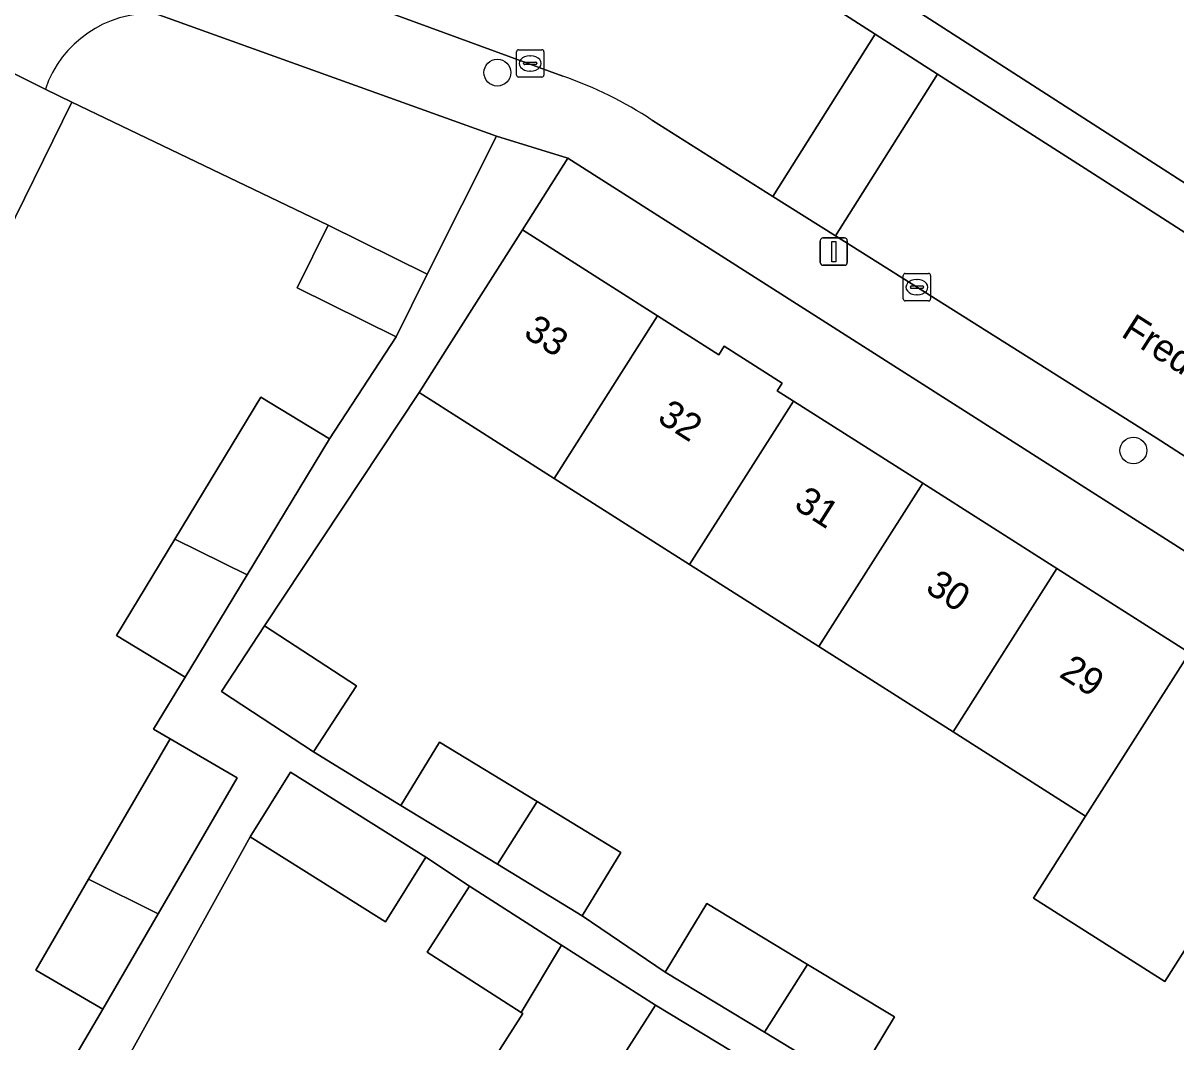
# Model space of a CAD drawing. Extents: x 160102 to 160934, y 382045 to 382923.
# Drawn here: x 160360.74 to 160402.88, y 382289.36 to 382326.59 of the extents above; entities that cross this region are included whole.
import ezdxf

# ---------------------------------------------------------------- set-up
doc = ezdxf.new("R2010")
doc.units = 0
for name, color, linetype in [('IMGEO_Boom', 7, 'Continuous'), ('IMGEO_Erf', 7, 'Continuous'), ('IMGEO_Groenvoorziening', 7, 'Continuous'), ('IMGEO_Kolk', 7, 'Continuous'), ('IMGEO_Lichtmast', 7, 'Continuous'), ('IMGEO_Openbare_ruimte_label', 7, 'Continuous'), ('IMGEO_Pand', 7, 'Continuous'), ('IMGEO_Pand_nummerreeks', 7, 'Continuous'), ('IMGEO_Rijbaan_lokaal_open', 7, 'Continuous'), ('IMGEO_Voetpad_open', 7, 'Continuous')]:
    doc.layers.add(name, color=color, linetype=linetype)

msp = doc.modelspace()

# ---------------------------------------------------------------- linework, layer by layer
at = {"layer": 'IMGEO_Boom'}
for centre in [(160378.074, 382324.78), (160401.321, 382310.971)]:
    msp.add_circle(centre, 0.489, dxfattribs=at)
at = {"layer": 'IMGEO_Erf'}
for points in [[(160366.666, 382302.692), (160364.152, 382304.216), (160366.28, 382307.729), (160369.425, 382312.919), (160371.939, 382311.396), (160374.379, 382315.121), (160370.755, 382316.911), (160371.89, 382319.21), (160362.523, 382323.7), (160359.744, 382318.076), (160359.198, 382317.036), (160358.065, 382314.742), (160360.27, 382313.652), (160359.092, 382311.269), (160359.529, 382311.053), (160356.868, 382305.666), (160354.057, 382299.975), (160351.44, 382301.267), (160348.559, 382295.436), (160345.757, 382289.765), (160342.922, 382291.166)], [(160404.372, 382294.56), (160402.466, 382291.561), (160397.668, 382294.61), (160399.574, 382297.609), (160394.734, 382300.685), (160389.827, 382303.803), (160385.101, 382306.807), (160380.151, 382309.953), (160375.213, 382313.091), (160369.561, 382304.569), (160372.929, 382302.375), (160371.358, 382299.964), (160374.551, 382297.996), (160375.956, 382300.308), (160379.525, 382298.139), (160382.583, 382296.281), (160381.178, 382293.969), (160384.206, 382291.908), (160385.728, 382294.422), (160389.415, 382292.19), (160392.59, 382290.269), (160391.068, 382287.755)], [(160344.039, 382286.352), (160356.664, 382278.779), (160358.695, 382282.138), (160355.236, 382284.213), (160356.54, 382286.388), (160359.999, 382284.313), (160360.175, 382284.614), (160355.353, 382287.424), (160357.305, 382290.773), (160362.134, 382287.959), (160363.655, 382290.557), (160361.206, 382291.98), (160363.135, 382295.3), (160366.118, 382300.431), (160365.51, 382300.785), (160366.666, 382302.692)], [(160377.525, 382288.071), (160379.001, 382290.4), (160378.944, 382290.437), (160375.51, 382292.635), (160377.056, 382295.05), (160375.46, 382296.106), (160373.982, 382293.75), (160371.619, 382295.234), (160369.034, 382296.857), (160363.795, 382287.392)], [(160386.658, 382289.004), (160383.854, 382290.698), (160380.822, 382285.961)]]:
    msp.add_lwpolyline(points, dxfattribs=at)
msp.add_lwpolyline([(160380.656, 382321.65), (160378.99, 382319.034), (160383.927, 382315.896), (160386.169, 382314.471), (160386.366, 382314.781), (160388.486, 382313.433), (160388.307, 382313.152), (160388.895, 382312.778), (160393.622, 382309.774), (160398.528, 382306.656), (160403.368, 382303.58), (160408.166, 382300.531), (160413.128, 382297.377), (160418.16, 382294.179), (160419.783, 382296.727)], close=True, dxfattribs=at)
at = {"layer": 'IMGEO_Groenvoorziening'}
msp.add_lwpolyline([(160437.773, 382324.41), (160408.75, 382345.566), (160387.099, 382331.11), (160425.707, 382306.276)], close=True, dxfattribs=at)
msp.add_lwpolyline([(160361.552, 382324.18), (160362.523, 382323.7), (160371.89, 382319.21), (160375.514, 382317.42), (160378.037, 382322.453), (160365.563, 382326.947)], dxfattribs=at)
msp.add_arc((160365.426, 382322.855), 4.094, 88.0823, 161.1176, dxfattribs=at)
at = {"layer": 'IMGEO_Kolk'}
for p, q in [((160378.85, 382325.617), (160379.702, 382325.617)), ((160378.775, 382324.691), (160378.775, 382325.543)), ((160379.077, 382325.16), (160379.475, 382325.16)), ((160379.263, 382325.397), (160379.288, 382325.397)), ((160379.776, 382325.543), (160379.776, 382324.691)), ((160379.034, 382325.111), (160379.034, 382325.123)), ((160379.472, 382325.074), (160379.074, 382325.074)), ((160379.286, 382324.837), (160379.261, 382324.837)), ((160379.518, 382325.123), (160379.518, 382325.111)), ((160379.702, 382324.617), (160378.85, 382324.617)), ((160392.91, 382316.514), (160392.91, 382317.366)), ((160392.985, 382317.44), (160393.837, 382317.44)), ((160393.398, 382317.22), (160393.423, 382317.22)), ((160393.911, 382317.366), (160393.911, 382316.514)), ((160393.169, 382316.934), (160393.169, 382316.946)), ((160393.607, 382316.897), (160393.209, 382316.897)), ((160393.212, 382316.983), (160393.61, 382316.983)), ((160393.653, 382316.946), (160393.653, 382316.934)), ((160393.837, 382316.44), (160392.985, 382316.44)), ((160393.421, 382316.66), (160393.396, 382316.66))]:
    msp.add_line(p, q, dxfattribs=at)
for points in [[(160378.85, 382325.617), (160379.702, 382325.617)], [(160378.775, 382324.691), (160378.775, 382325.543)], [(160379.776, 382325.543), (160379.776, 382324.691)], [(160379.702, 382324.617), (160378.85, 382324.617)], [(160392.91, 382316.514), (160392.91, 382317.366)], [(160392.985, 382317.44), (160393.837, 382317.44)], [(160393.911, 382317.366), (160393.911, 382316.514)], [(160393.837, 382316.44), (160392.985, 382316.44)]]:
    msp.add_lwpolyline(points, dxfattribs=at)
for centre, radius, start, end in [((160378.852, 382325.541), 0.0765, 91.552, 178.448), ((160378.852, 382325.541), 0.0765, 91.552, 178.448), ((160379.7, 382325.541), 0.0765, 1.552, 88.448), ((160379.7, 382325.541), 0.0765, 1.552, 88.448), ((160379.074, 382325.12), 0.0403, 85.8775, 175.7526), ((160379.479, 382325.122), 0.0386, 1.7309, 96.639), ((160379.071, 382325.11), 0.0366, 178.938, 274.7102), ((160379.475, 382325.117), 0.043, 264.8664, 352.4533), ((160378.852, 382324.693), 0.0765, 181.552, 268.448), ((160378.852, 382324.693), 0.0765, 181.552, 268.448), ((160379.7, 382324.693), 0.0765, 271.552, 358.448), ((160379.7, 382324.693), 0.0765, 271.552, 358.448), ((160392.987, 382317.364), 0.0765, 91.552, 178.448), ((160392.987, 382317.364), 0.0765, 91.552, 178.448), ((160393.835, 382317.364), 0.0765, 1.552, 88.448), ((160393.835, 382317.364), 0.0765, 1.552, 88.448), ((160393.209, 382316.943), 0.0403, 85.8775, 175.7526), ((160393.206, 382316.933), 0.0366, 178.938, 274.7102), ((160393.61, 382316.94), 0.043, 264.8664, 352.4533), ((160393.614, 382316.945), 0.0386, 1.7309, 96.639), ((160392.987, 382316.516), 0.0765, 181.552, 268.448), ((160392.987, 382316.516), 0.0765, 181.552, 268.448), ((160393.835, 382316.516), 0.0765, 271.552, 358.448), ((160393.835, 382316.516), 0.0765, 271.552, 358.448)]:
    msp.add_arc(centre, radius, start, end, dxfattribs=at)
for centre, major_axis, ratio, start_param, end_param in [((160379.262, 382325.117), (-0.387, 0.002), 0.722429, 4.712389, 7.853982), ((160379.287, 382325.117), (-0.39, 0.002), 0.717154, 1.570796, 4.712389), ((160393.397, 382316.94), (-0.387, 0.002), 0.722429, 4.712389, 7.853982), ((160393.422, 382316.94), (-0.39, 0.002), 0.717154, 1.570796, 4.712389)]:
    msp.add_ellipse(centre, major_axis=major_axis, ratio=ratio, start_param=start_param, end_param=end_param, dxfattribs=at)
at = {"layer": 'IMGEO_Lichtmast'}
for p, q in [((160389.876, 382317.839), (160389.876, 382318.639)), ((160389.876, 382318.639), (160389.876, 382317.839)), ((160389.976, 382318.739), (160390.766, 382318.739)), ((160390.766, 382318.739), (160389.976, 382318.739)), ((160390.866, 382318.639), (160390.866, 382317.839)), ((160390.866, 382317.839), (160390.866, 382318.639)), ((160390.766, 382317.739), (160389.976, 382317.739)), ((160389.976, 382317.739), (160390.766, 382317.739))]:
    msp.add_line(p, q, dxfattribs=at)
msp.add_lwpolyline([(160390.296, 382318.614), (160390.446, 382318.614), (160390.446, 382317.864), (160390.296, 382317.864), (160390.296, 382318.614)], dxfattribs=at)
for centre, start, end in [((160389.976, 382318.639), 90, 180), ((160389.976, 382318.639), 90, 180), ((160390.766, 382318.639), 0, 90), ((160390.766, 382318.639), 360, 90), ((160389.976, 382317.839), 180, 270), ((160389.976, 382317.839), 180, 270), ((160390.766, 382317.839), 270, 0), ((160390.766, 382317.839), 270, 0)]:
    msp.add_arc(centre, 0.1, start, end, dxfattribs=at)
at = {"layer": 'IMGEO_Pand'}
for points in [[(160362.523, 382323.7), (160361.552, 382324.18), (160359.856, 382325.018), (160356.473, 382326.689), (160353.694, 382321.065), (160359.744, 382318.076)], [(160371.89, 382319.21), (160370.755, 382316.911), (160374.379, 382315.121), (160375.514, 382317.42)], [(160383.927, 382315.896), (160378.99, 382319.034), (160376.309, 382314.815), (160375.213, 382313.091), (160380.151, 382309.953)], [(160385.101, 382306.807), (160388.895, 382312.778), (160388.307, 382313.152), (160388.486, 382313.433), (160386.366, 382314.781), (160386.169, 382314.471), (160383.927, 382315.896), (160380.151, 382309.953)], [(160368.926, 382306.422), (160371.939, 382311.396), (160369.425, 382312.919), (160366.28, 382307.729)], [(160393.622, 382309.774), (160388.895, 382312.778), (160385.101, 382306.807), (160389.827, 382303.803)], [(160393.622, 382309.774), (160389.827, 382303.803), (160394.734, 382300.685), (160398.528, 382306.656)], [(160368.926, 382306.422), (160366.28, 382307.729), (160364.152, 382304.216), (160366.666, 382302.692)], [(160403.368, 382303.58), (160398.528, 382306.656), (160394.734, 382300.685), (160399.574, 382297.609)], [(160369.561, 382304.569), (160367.99, 382302.158), (160371.358, 382299.964), (160372.929, 382302.375)], [(160403.368, 382303.58), (160399.574, 382297.609), (160397.668, 382294.61), (160402.466, 382291.561), (160404.372, 382294.56), (160408.166, 382300.531)], [(160365.68, 382294.043), (160368.566, 382299.008), (160366.118, 382300.431), (160363.135, 382295.3)], [(160378.074, 382295.855), (160379.525, 382298.139), (160375.956, 382300.308), (160374.551, 382297.996)], [(160375.46, 382296.106), (160370.513, 382299.212), (160369.034, 382296.857), (160371.619, 382295.234), (160373.982, 382293.75)], [(160378.074, 382295.855), (160381.178, 382293.969), (160382.583, 382296.281), (160379.525, 382298.139)], [(160365.68, 382294.043), (160363.135, 382295.3), (160361.206, 382291.98), (160363.655, 382290.557)], [(160378.944, 382290.437), (160380.419, 382292.897), (160377.056, 382295.05), (160375.51, 382292.635)], [(160387.838, 382289.71), (160389.415, 382292.19), (160385.728, 382294.422), (160384.206, 382291.908)], [(160378.944, 382290.437), (160379.001, 382290.4), (160377.525, 382288.071), (160380.822, 382285.961), (160383.854, 382290.698), (160380.419, 382292.897)], [(160387.838, 382289.71), (160391.068, 382287.755), (160392.59, 382290.269), (160389.415, 382292.19)]]:
    msp.add_lwpolyline(points, close=True, dxfattribs=at)
at = {"layer": 'IMGEO_Rijbaan_lokaal_open'}
for points in [[(160391.886, 382326.191), (160382.828, 382331.994), (160381.398, 382332.855), (160367.385, 382337.325), (160359.259, 382338.878), (160358.478, 382332.777), (160374.104, 382326.98), (160380.469, 382324.649)], [(160383.739, 382323.036), (160388.146, 382320.258), (160391.886, 382326.191)]]:
    msp.add_lwpolyline(points, dxfattribs=at)
for points in [[(160388.146, 382320.258), (160390.438, 382318.814), (160394.166, 382324.73), (160391.886, 382326.191)], [(160390.438, 382318.814), (160402.157, 382311.428), (160432.528, 382291.84), (160436.26, 382297.701), (160399.869, 382321.076), (160394.166, 382324.73)]]:
    msp.add_lwpolyline(points, close=True, dxfattribs=at)
msp.add_arc((160375.807, 382311.077), 14.35, 56.4452, 71.0431, dxfattribs=at)
at = {"layer": 'IMGEO_Voetpad_open'}
for points in [[(160448.462, 382291.69), (160445.435, 382293.62), (160444.821, 382294.012), (160440.669, 382296.658), (160440.293, 382296.898), (160439.57, 382297.359), (160435.995, 382299.658), (160435.719, 382299.836), (160431.511, 382302.543), (160430.958, 382302.899), (160429.774, 382303.66), (160425.707, 382306.276), (160387.099, 382331.11), (160382.328, 382334.109), (160379.791, 382335.33)], [(160380.469, 382324.649), (160374.104, 382326.98), (160358.478, 382332.777), (160355.602, 382327.113), (160356.473, 382326.689), (160359.856, 382325.018), (160361.552, 382324.18)], [(160381.398, 382332.855), (160382.828, 382331.994), (160391.886, 382326.191), (160394.166, 382324.73), (160399.869, 382321.076), (160436.26, 382297.701), (160438.55, 382296.23), (160439.347, 382295.718), (160446.656, 382291.054), (160449.124, 382289.462), (160449.47, 382289.239), (160450.03, 382290.115), (160456.682, 382285.86), (160456.122, 382284.984), (160456.962, 382284.447)], [(160365.563, 382326.947), (160378.037, 382322.453), (160380.656, 382321.65), (160419.783, 382296.727), (160421.207, 382295.82), (160447.959, 382278.78)], [(160432.528, 382291.84), (160402.157, 382311.428), (160390.438, 382318.814), (160388.146, 382320.258), (160383.739, 382323.036)], [(160391.068, 382287.755), (160387.838, 382289.71), (160384.206, 382291.908), (160381.178, 382293.969), (160378.074, 382295.855), (160374.551, 382297.996), (160371.358, 382299.964), (160367.99, 382302.158), (160369.561, 382304.569), (160375.213, 382313.091), (160376.309, 382314.815), (160378.99, 382319.034), (160380.656, 382321.65), (160378.037, 382322.453), (160375.514, 382317.42), (160374.379, 382315.121), (160371.939, 382311.396), (160368.926, 382306.422), (160366.666, 382302.692), (160365.51, 382300.785), (160366.118, 382300.431), (160368.566, 382299.008), (160365.68, 382294.043), (160363.655, 382290.557), (160362.134, 382287.959)], [(160363.795, 382287.392), (160369.034, 382296.857), (160370.513, 382299.212), (160375.46, 382296.106), (160377.056, 382295.05), (160380.419, 382292.897), (160383.854, 382290.698), (160386.658, 382289.004)]]:
    msp.add_lwpolyline(points, dxfattribs=at)
for centre, radius, start, end in [((160365.426, 382322.855), 4.094, 88.0823, 161.1176), ((160375.807, 382311.077), 14.35, 56.4452, 71.0431)]:
    msp.add_arc(centre, radius, start, end, dxfattribs=at)

# ---------------------------------------------------------------- texts
at = {"layer": 'IMGEO_Openbare_ruimte_label'}
msp.add_text('Frederik Hendrikplein', height=1, rotation=327.5024, dxfattribs=at).set_placement((160400.831, 382315.169))
at = {"layer": 'IMGEO_Pand_nummerreeks'}
for s, p in [('33', (160378.983, 382315.154)), ('32', (160383.877, 382312.049)), ('31', (160388.871, 382308.88)), ('30', (160393.674, 382305.832)), ('29', (160398.568, 382302.726))]:
    msp.add_text(s, height=1, rotation=327.6032, dxfattribs=at).set_placement(p)

doc.saveas('drawing.dxf')
